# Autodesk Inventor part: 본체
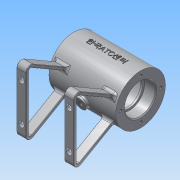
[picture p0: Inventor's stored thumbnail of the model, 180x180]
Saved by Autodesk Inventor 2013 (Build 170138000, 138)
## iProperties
Created: 2016-03
Part Number: 본체
Material: 알루미늄 6061
Document SubType Name: Modeling
Designer: Administrator
Density: 2.71 g/cm^3
Mass: 210.891 g
Surface Area: 328.798 cm^2
Volume: 77.8195 cm^3
Author: Administrator
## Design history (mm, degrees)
sketch "스케치1"
  geometry: L1 (-35, 0)-(35, 0); L2 (35, 0)-(35, 26); L3 (35, 26)-(-35, 26); L4 (-35, 26)-(-35, 0); 2 further points
  constraints: 8 end point, 2 perpendicular, 1 coincident, 1 horizontal, 1 midpoint, 1 parallel
  dimensions: "d0" = 70 distance of L1.start L1.end; "d2" = 52 diameter of L3 L1
revolve "회전1" sketch "스케치1" stored, may be unused: angle "d3" = 90 deg
sketch "스케치2"
  geometry: C1 r 26 at (0, 0) reference
hole "구멍1" sketch "스케치2" at (0, 0) diameter "d4" = 28; stored, may be unused: countersink angle "d8" = 90 deg, drill point angle "d10" = 0 deg; dims "d5" = 6, "d6" = 32, "d7" = 12, "d9" = 14
sketch "스케치3"
  geometry: C1 r 26 at (0, 0) reference
hole "구멍2" sketch "스케치3" at (0, 0) diameter "d11" = 28; stored, may be unused: countersink angle "d15" = 90 deg, drill point angle "d17" = 0 deg; dims "d12" = 6, "d13" = 32, "d14" = 12, "d16" = 14
sketch "스케치4"
  geometry: C1 r 14 at (0, 0) reference; C2 r 21 at (0, 0)
  constraints: 1 centre point, 1 coincident
  dimensions: "d18" = 42 diameter of C2
extrude "돌출1" cut sketch "스케치4" distance "d19" = 42; taper "d20" = 0 deg
chamfer "모따기1" distance "d21" = 1; stored, may be unused: second distance "d22" = 2, angle "d23" = 45 deg
fillet "모깎기2" dims "d25" = 0.3
node "작업 평면1"
sketch "스케치5"
  geometry: C1 r 5 at (0, 0); 1 further point
  constraints: 1 centre point, 1 coincident
  dimensions: "d27" = 10 diameter of C1
extrude "돌출2" join sketch "스케치5" stored distance "d28" = 42; taper "d29" = 0 deg
sketch "스케치6"
  geometry: C1 r 5 at (0, 0) reference
hole "구멍3" sketch "스케치6" at (0, 0) diameter "d30" = 5.188; stored, may be unused: countersink angle "d34" = 90 deg, drill point angle "d36" = 0 deg; dims "d31" = 6, "d32" = 32, "d33" = 12, "d35" = 14
fillet "모깎기3" dims "d37" = 2
node "작업 평면2"
node "작업 평면4"
  node "작업 평면3"
sketch "스케치9"
  geometry: C1 r 6 at (0, 0); 1 further point
  constraints: 1 centre point, 1 coincident
  dimensions: "d42" = 12 diameter of C1
extrude "돌출3" join sketch "스케치9" stored distance "d43" = 42; taper "d44" = 0 deg
sketch "스케치10"
  geometry: C1 r 6 at (0, 0) reference
hole "구멍4" sketch "스케치10" at (0, 0) diameter "d45" = 5.188; stored, may be unused: countersink angle "d49" = 90 deg, drill point angle "d51" = 0 deg; dims "d46" = 6, "d47" = 32, "d48" = 12, "d50" = 14
fillet "모깎기4" dims "d52" = 2
sketch "스케치11"
  geometry: C1 r 26 at (0, 0) reference; 1 further point
  constraints: 1 vertical alignment
  dimensions: "d53" = 21 distance of C1.centre point (0, 21)
hole "구멍5" sketch "스케치11" at (0, 21) diameter "d54" = 3.242; stored, may be unused: countersink angle "d58" = 90 deg, drill point angle "d60" = 118 deg; dims "d55" = 8, "d56" = 32, "d57" = 12, "d59" = 10
node "작업 평면5"
fillet "모깎기12" dims "d110" = 3
sketch "스케치18"
  geometry: 1 further point
node "작업 평면9"
sketch "스케치19"
  geometry: L1 (0, 0)-(-65, 0); L2 (-22.517, 13)-(-65, 37.528); L3 (-65, 0)-(-65, 37.528); L4 (0, 0)-(-22.517, 13); L5 (-22.517, -13)-(-65, -37.528); L6 (-65, 0)-(-65, -37.528); L7 (0, 0)-(-22.517, -13); A1 r 26 centre (0, 0) between (-22.517, -13) and (-22.517, 13) reference; 3 further points
  constraints: 14 end point, 2 point on circle, 2 point on line, 2 symmetric about line, 1 collinear, 1 horizontal, 1 perpendicular, 2 other
  dimensions: "d112" = 65 distance of L1.start L1.end; "d113" = 30 deg angle of L1 L2
extrude "돌출9" join sketch "스케치19" distance "d114" = 10; taper "d115" = 0 deg
sketch "스케치20"
  geometry: L1 (-37.528, -65)-(37.528, -65) reference; L2 (37.528, -65)-(13, -22.517) reference; L3 (-13, -22.517)-(-37.528, -65) reference; L4 (10.315, -23.866)-(32.332, -62); L5 (32.332, -62)-(-32.332, -62); L6 (-32.332, -62)-(-10.315, -23.866); A1 r 26 centre (0, 0) between (-13, -22.517) and (13, -22.517) reference
  constraints: 6 end point, 2 point on circle
  dimensions: "d116" = 3 distance between parallel lines of L2 L4; "d117" = 3 distance between parallel lines of L6 L3; "d118" = 3 distance between parallel lines of L1 L5
extrude "돌출10" cut sketch "스케치20" distance "d119" = 10; taper "d120" = 0 deg
fillet "모깎기13" dims "d121" = 5, "d122" = 2
fillet "모깎기14" dims "d123" = 0.5
sketch "스케치21"
  geometry: L1 (-10, 57.735)-(0, 57.735) reference; C1 r 3 at (-5, 48.868); 2 further points
  constraints: 1 centre point, 1 midpoint, 1 vertical alignment
  dimensions: "d124" = 6 diameter of C1; "d125" = 20 vertical distance of point (-30, 28.868) C1.centre
extrude "돌출11" cut sketch "스케치21" stored distance "d126" = 10; taper "d127" = 0 deg
fillet "모깎기15" dims "d131" = 3
node "작업 평면10"
sketch "스케치22"
  geometry: 2 further points
  constraints: 1 coincident, 1 other
feature "엠보싱2" sketch "스케치22" dims "d0" = 70, "d2" = 52, "d132" = 0.5, "d133" = 0
fillet "모깎기16" dims "d134" = 0.5
node "솔리드1"
pattern_circular "원형 패턴1" dims angle "d62" = 360 deg
mirror "대칭1"
pattern_linear "직사각형 패턴3" dims "d130" = 40
mirror "대칭4"
node "절단 모서리 투영3"
other parameters: "d26" = 29, "d39" = 15 deg, "d40" = 15 deg, "d41" = -29, "d64" = -65
